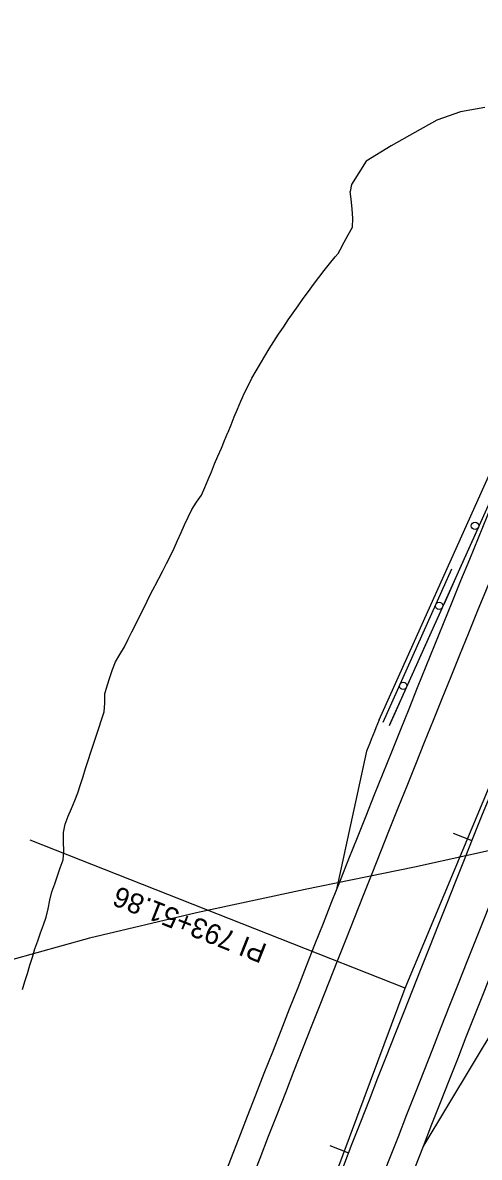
# Model space of a CAD drawing. Extents: x 1237212 to 1293764, y 379349 to 410301.
# Drawn here: x 1283156.7 to 1283292.5, y 403550.3 to 403888.2 of the extents above; entities that cross this region are included whole.
import ezdxf

# ---------------------------------------------------------------- set-up
doc = ezdxf.new("R2010")
doc.units = 0
for name, color, linetype in [('B-Tbl-Title Block', 7, 'Continuous'), ('B-Title Block (No Plot)', 7, 'Continuous'), ('R_Axis_Annotation', 7, 'Continuous'), ('R_Exist Surface', 7, 'Continuous'), ('R_Grid', 7, 'Continuous'), ('R_Grid Annot', 7, 'Continuous'), ('R_Prop Surface', 7, 'Continuous'), ('R_Shld', 7, 'Continuous')]:
    doc.layers.add(name, color=color, linetype=linetype)

msp = doc.modelspace()

# ---------------------------------------------------------------- linework, layer by layer
at = {"layer": 'B-Tbl-Title Block'}
for radius in [11483.16, 11447.16]:
    msp.add_arc((1293930.9, 399391.32), radius, 157.333333, 159.572534, dxfattribs=at)
at = {"layer": 'B-Title Block (No Plot)'}
msp.add_arc((1293930.9, 399391.32), 11459.16, 157.333333, 159.572534, dxfattribs=at)
msp.add_arc((1293930.9, 399391.32), 11459.16, 157.333333, 159.572534, dxfattribs=at)
at = {"layer": 'R_Axis_Annotation'}
msp.add_lwpolyline([(1283715.99, 403909.66), (1283691.25, 403887.11), (1283666.96, 403863.7), (1283642.92, 403839.5), (1283618.78, 403815.12), (1283594.64, 403790.92), (1283570.05, 403767.27), (1283545.16, 403744.59), (1283519.52, 403723.51), (1283493.14, 403704.25), (1283464.66, 403688.78), (1283433.84, 403677.4), (1283401.78, 403668.46), (1283369.46, 403660.32), (1283337.74, 403651.63), (1283305.58, 403643.85), (1283273.27, 403636.74), (1283240.75, 403630.06), (1283208.44, 403623.14), (1283176.57, 403615.54), (1283145.16, 403606.85)], dxfattribs=at)
at = {"layer": 'R_Exist Surface'}
for points in [[(1283294.15, 403862.87), (1283286.96, 403861.62), (1283279.93, 403859.17), (1283273.32, 403855.51), (1283266.36, 403851.47), (1283258.9, 403846.92), (1283254.56, 403839.97), (1283254.17, 403837.89)], [(1283156.65, 403600.24), (1283157.38, 403602.66), (1283158.12, 403605.08), (1283158.85, 403607.51), (1283159.58, 403609.93), (1283160.33, 403612.35), (1283161.18, 403614.73), (1283162.03, 403617.11), (1283162.87, 403619.48), (1283163.72, 403621.86), (1283164.32, 403624.34), (1283164.8, 403626.86), (1283165.38, 403629.34), (1283166.22, 403631.73), (1283167.05, 403634.11), (1283167.88, 403636.5), (1283168.71, 403638.89), (1283168.92, 403641.52), (1283168.87, 403644.25), (1283168.81, 403646.99), (1283169.32, 403649.5), (1283170.27, 403651.84), (1283171.23, 403654.18), (1283172.18, 403656.52), (1283173.08, 403658.88), (1283173.87, 403661.28), (1283174.65, 403663.69), (1283175.43, 403666.1), (1283176.21, 403668.5), (1283176.98, 403670.91), (1283177.76, 403673.32), (1283178.54, 403675.73), (1283179.33, 403678.13), (1283180.12, 403680.54), (1283180.91, 403682.94), (1283181.13, 403685.57), (1283181.17, 403688.28), (1283181.8, 403690.74), (1283182.61, 403693.14), (1283183.43, 403695.53), (1283184.35, 403697.88), (1283185.65, 403700.08), (1283186.95, 403702.28), (1283188.08, 403704.55), (1283189.22, 403706.82), (1283190.36, 403709.08), (1283191.49, 403711.35), (1283192.61, 403713.62), (1283193.74, 403715.88), (1283194.87, 403718.15), (1283196.04, 403720.4), (1283196.1, 403720.53), (1283197.2, 403722.66), (1283198.37, 403724.91), (1283199.53, 403727.16), (1283200.66, 403729.43), (1283201.72, 403731.73), (1283202.77, 403734.02), (1283203.83, 403736.32), (1283204.88, 403738.62), (1283205.95, 403740.91), (1283207.06, 403743.18), (1283208.41, 403745.36), (1283209.86, 403747.5), (1283210.88, 403749.81), (1283211.86, 403752.14), (1283212.83, 403754.46), (1283213.81, 403756.79), (1283214.8, 403759.12), (1283215.82, 403761.43), (1283216.78, 403763.76), (1283217.74, 403766.1), (1283217.79, 403766.23), (1283218.7, 403768.43), (1283219.66, 403770.77), (1283220.61, 403773.1), (1283221.57, 403775.44), (1283222.05, 403776.6), (1283222.61, 403777.74), (1283223.74, 403780.01), (1283224.87, 403782.27), (1283226.13, 403784.48), (1283227.42, 403786.68), (1283228.73, 403788.87), (1283230.05, 403791.06), (1283231.38, 403793.24), (1283232.76, 403795.4), (1283234.25, 403797.52), (1283235.73, 403799.64), (1283237.19, 403801.77), (1283238.67, 403803.89), (1283240.17, 403806), (1283241.69, 403808.1), (1283243.24, 403810.19), (1283244.81, 403812.27), (1283246.41, 403814.34), (1283248.03, 403816.4), (1283249.71, 403818.43), (1283250.55, 403819.44), (1283251.16, 403820.56), (1283252.37, 403822.79), (1283253.58, 403825.02), (1283254.78, 403827.25), (1283254.97, 403829.9), (1283254.69, 403832.75), (1283254.4, 403835.61), (1283254.17, 403837.89)]]:
    msp.add_lwpolyline(points, dxfattribs=at)
at = {"layer": 'R_Grid'}
for points in [[(1283192.36, 403390.81), (1283270.52, 403600.67), (1283356.82, 403807.32)], [(1283270.52, 403600.67), (1283158.91, 403644.74)], [(1283270.52, 403600.67), (1283158.91, 403644.74)]]:
    msp.add_lwpolyline(points, dxfattribs=at)
at = {"layer": 'R_Grid Annot'}
for points in [[(1283284.77, 403646.86), (1283290.34, 403644.63)], [(1283284.77, 403646.86), (1283290.34, 403644.63)], [(1283248.04, 403553.8), (1283253.63, 403551.62)], [(1283248.04, 403553.8), (1283253.63, 403551.62)]]:
    msp.add_lwpolyline(points, dxfattribs=at)
at = {"layer": 'R_Prop Surface'}
msp.add_line((1283265.94, 403679.14), (1283307, 403770.74), dxfattribs=at)
for points in [[(1283287.16, 403726.47), (1283292.27, 403737.88)], [(1283282.05, 403715.06), (1283287.16, 403726.47)], [(1283284.28, 403725.41), (1283263.82, 403679.79)], [(1283276.48, 403702.65), (1283281.6, 403714.06)], [(1283271.37, 403691.25), (1283276.48, 403702.65)], [(1283265.81, 403678.84), (1283270.92, 403690.24)]]:
    msp.add_lwpolyline(points, dxfattribs=at)
for centre in [(1283291.27, 403738.33), (1283280.59, 403714.51), (1283269.92, 403690.69)]:
    msp.add_circle(centre, 1.1, dxfattribs=at)
at = {"layer": 'R_Shld'}
for p, q in [((1283262.75, 403680.57), (1283303.81, 403772.18)), ((1283259.01, 403671.26), (1283249.95, 403629.69)), ((1283297.75, 403590.06), (1283275.79, 403553.38))]:
    msp.add_line(p, q, dxfattribs=at)
for centre, radius, start, end in [((1293930.9, 399391.32), 11491.16, 157.381068, 159.572534), ((1293930.9, 399391.32), 11439.16, 157.333333, 159.572534), ((1293931.6, 399392.99), 11498.16, 158.105879, 158.155879)]:
    msp.add_arc(centre, radius, start, end, dxfattribs=at)

# ---------------------------------------------------------------- texts
at = {"layer": 'R_Grid'}
msp.add_text('PI 793+51.86', height=6, rotation=158.4529, dxfattribs=at).set_placement((1283229.77, 403613.54))
msp.add_text('PI 793+51.86', height=6, rotation=158.4529, dxfattribs=at).set_placement((1283229.77, 403613.54))

doc.saveas('drawing.dxf')
